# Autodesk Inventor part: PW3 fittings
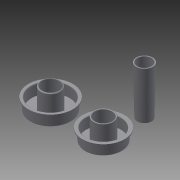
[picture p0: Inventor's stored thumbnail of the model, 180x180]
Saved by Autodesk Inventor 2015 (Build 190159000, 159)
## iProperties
Created: 2014-07
Part Number: PW3 fittings
Material: Generic
Document SubType Name: Modeling
Designer: Kay
Density: 1 g/cm^3
Appearance: Default
Author: Kay
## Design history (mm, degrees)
sketch "Sketch1"
  geometry: C1 r 9 at (0, 0); C2 r 10.2 at (0, 0); C3 r 19.275 at (0, 0); C4 r 18.075 at (0, 0); C5 r 21.075 at (0, 0); 1 further point
  constraints: 5 centre point, 2 coincident
  dimensions: "d0" = 18 diameter of C1; "d1" = 1.2 radial gap between concentric circles of C1 C2; "d2" = 38.55 diameter of C3; "d3" = 1.2 radial gap between concentric circles of C3 C4; "d4" = 3 radial gap between concentric circles of C4 C5
extrude "Extrusion1" new body sketch "Sketch1" distance "d5" = 12.5; taper "d6" = 0 deg
extrude "Extrusion2" join sketch "Sketch1" distance "d7" = 1.2; taper "d8" = 0 deg
extrude "Extrusion3" join sketch "Sketch1" distance "d9" = 22.5; taper "d10" = 0 deg
workplane "Work Plane1"
sketch "Sketch2"
  geometry: C1 r 19.275 at (0, 0); C2 r 21.475 at (0, 0); 1 further point
  constraints: 2 centre point
  dimensions: "d12" = 38.55 diameter of C1
extrude "Extrusion4" join sketch "Sketch2" distance "d13" = 1.2; taper "d14" = 0 deg
sketch "Sketch3"
  geometry: C1 r 7.5 at (42.826, 0); C2 r 8.5 at (42.826, 0); 1 further point
  constraints: 2 centre point
  dimensions: "d16" = 15 diameter of C1; "d17" = 1 radial gap between concentric circles of C1 C2
workplane "Work Plane2"
sketch "Sketch4"
  geometry: C1 r 7.5 at (42.826, 0); C2 r 6.5 at (42.826, 0); 1 further point
  constraints: 2 centre point
  dimensions: "d19" = 15 diameter of C1; "d21" = 1 radial gap between concentric circles of C1 C2
loft "Loft1" dims "d22" = 0, "d23" = 90 deg, "d24" = 0, "d25" = 90 deg
loft "Loft2" dims "d26" = 0, "d27" = 90 deg, "d28" = 0, "d29" = 90 deg
combine "Combine1"
  body "Solid3"
fillet "Fillet2" dims "d33" = 2
fillet "Fillet3" dims "d34" = 1
fillet "Fillet4" dims "d35" = 0.5
fillet "Fillet5" dims "d36" = 1
node "Direct Edit1"
fillet "Fillet6" dims "d38" = 1
feature "Move Body2"
sketch "Sketch5"
  geometry: C1 r 9 at (0, -55.331); C2 r 10.2 at (0, -55.331); C3 r 21.125 at (0, -55.331); C4 r 19.925 at (0, -55.331); C5 r 23.125 at (0, -55.331); 1 further point
  constraints: 5 centre point, 1 coincident
  dimensions: "d42" = 18 diameter of C1; "d43" = 1.2 radial gap between concentric circles of C1 C2; "d44" = 42.25 diameter of C3; "d45" = 1.2 radial gap between concentric circles of C3 C4; "d46" = 2 radial gap between concentric circles of C3 C5
sketch "Sketch6"
  geometry: C1 r 9 at (0, -55.331); C2 r 10.2 at (0, -55.331); C3 r 21.125 at (0, -55.331); C4 r 19.925 at (0, -55.331); C5 r 23.125 at (0, -55.331); 1 further point
  constraints: 5 centre point, 1 coincident
  dimensions: "d47" = 18 diameter of C1; "d48" = 1.2 radial gap between concentric circles of C1 C2; "d49" = 42.25 diameter of C3; "d50" = 1.2 radial gap between concentric circles of C3 C4; "d51" = 2 radial gap between concentric circles of C3 C5
extrude "Extrusion5" new body sketch "Sketch6" distance "d52" = 1.2; taper "d53" = 0 deg
extrude "Extrusion6" join sketch "Sketch6" distance "d54" = 12.5; taper "d55" = 0 deg
extrude "Extrusion7" join sketch "Sketch6" distance "d56" = 22.5; taper "d57" = 0 deg
extrude "Extrusion8" join sketch "Sketch5" distance "d58" = 1.2; taper "d59" = 0 deg
fillet "Fillet7" dims "d60" = 1
fillet "Fillet8" dims "d61" = 2
fillet "Fillet9" dims "d62" = 1
fillet "Fillet10" dims "d63" = 1
fillet "Fillet11" dims "d64" = 1
fillet "Fillet12" dims "d65" = 1
node "Stand 38.5"
node "Extension"
node "Stand 42.25"
feature "Size1" dims "d37" = 0.5
other parameters: "d11" = -12.5, "d39" = 0, "d40" = 0
